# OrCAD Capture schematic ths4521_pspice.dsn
size A
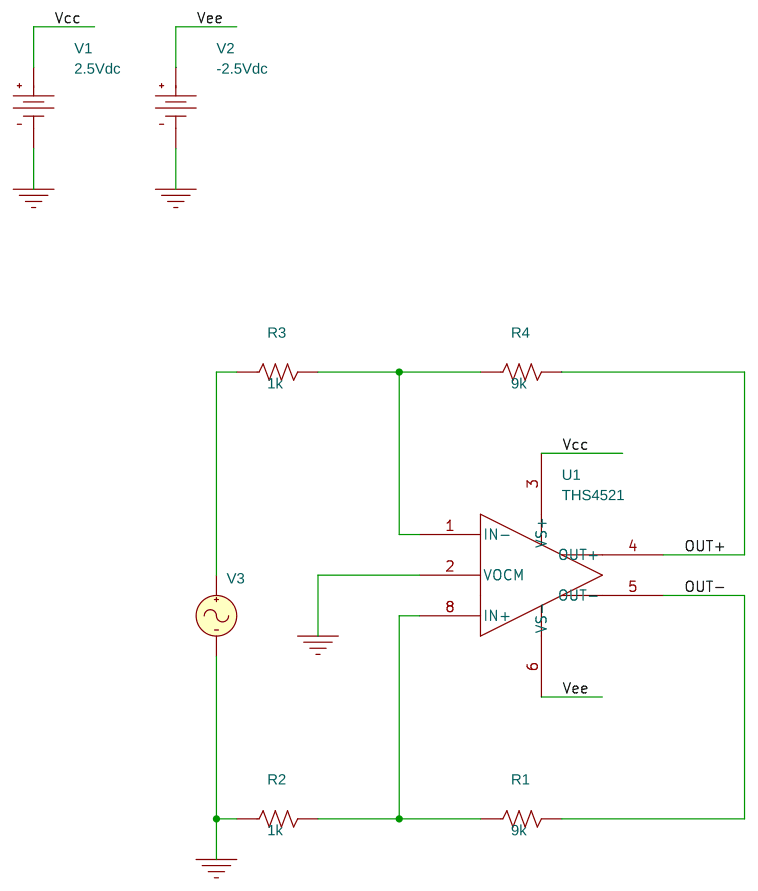
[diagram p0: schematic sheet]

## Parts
R1  9k  [AX/RC05]
R2  1k  [AX/RC05]
R3  1k  [AX/RC05]
R4  9k  [AX/RC05]
U1  THS4521
V1  VDC
V2  VDC
V3  VAC

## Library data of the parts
R1-R4 = R
U1 = THS4521
V1 = VDC: DC: 2.5Vdc
V2 = VDC: DC: -2.5Vdc
V3 = VAC

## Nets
Vcc: U1.3(VS+) V1.0(+)
Vee: U1.6(VS-) V2.0(+)
0: R2.1 U1.2(VOCM) V1.1(-) V2.1(-) V3.2(-)
OUT+: R4.2 U1.4(OUT+)
OUT-: R1.2 U1.5(OUT-)
N02463: R1.1 R2.2 U1.8(IN+)
N02936: R3.1 V3.1(+)
N02946: R3.2 R4.1 U1.1(IN-)
